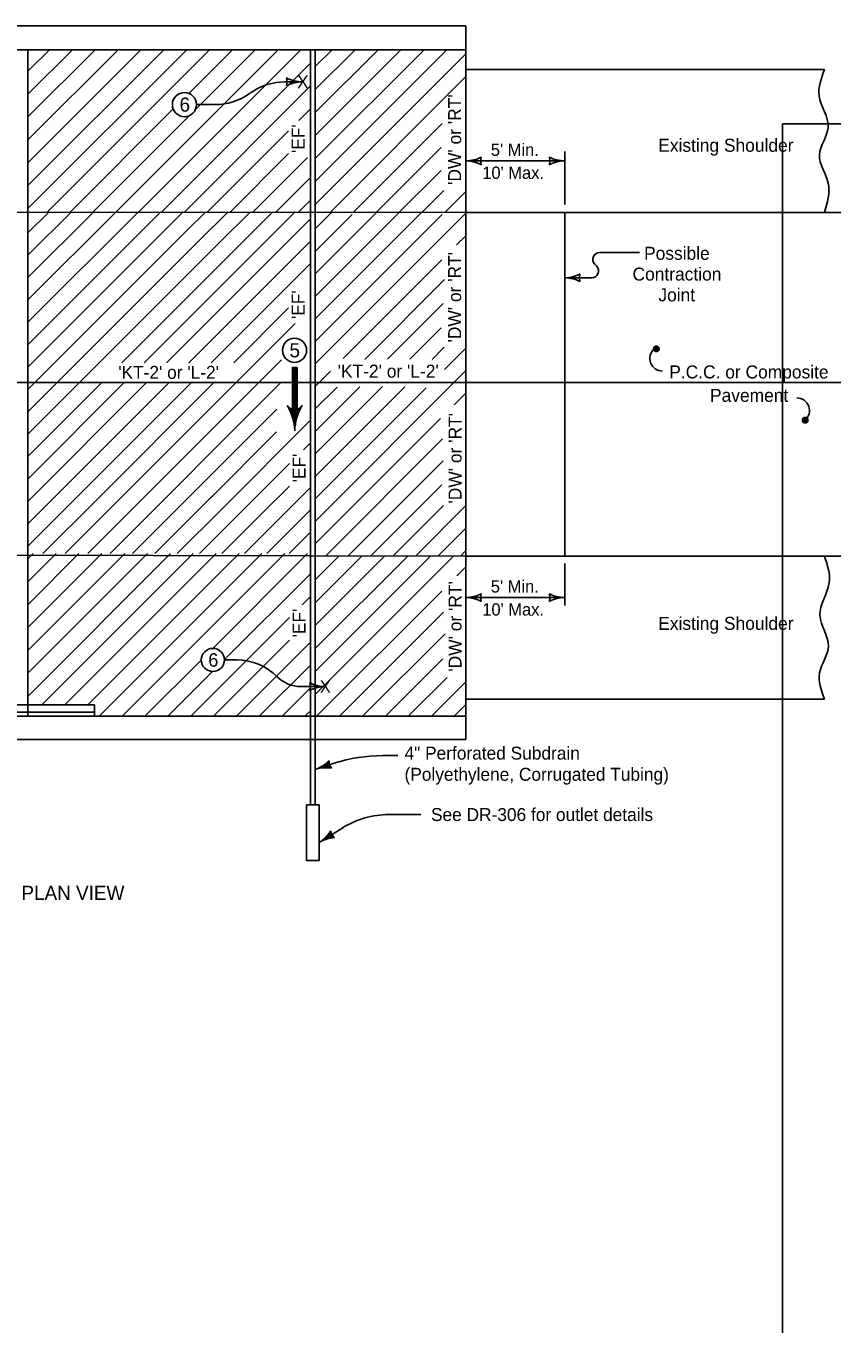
# Model space of a CAD drawing. Extents: x 5546 to 81668, y 3174 to 15999.
# Drawn here: x 20614 to 21661, y 14241 to 15927 of the extents above; entities that cross this region are included whole.
import ezdxf

# ---------------------------------------------------------------- set-up
doc = ezdxf.new("R2010")
doc.units = 0
for name, color, linetype in [('Level 61', 7, 'Continuous'), ('PS_BOLT', 7, 'Continuous'), ('PS_DAWA', 7, 'Continuous'), ('PS_DIM', 7, 'Continuous')]:
    doc.layers.add(name, color=color, linetype=linetype)

msp = doc.modelspace()

# ---------------------------------------------------------------- linework, layer by layer
msp.add_line((20246, 15896.5), (21185.1, 15896.5))
at = {"layer": 'Level 61'}
msp.add_lwpolyline([(21596.3, 15800.4), (24731.3, 15800.4), (24731.3, 13780.4), (21596.3, 13780.4)], close=True, dxfattribs=at)
at = {"layer": 'PS_BOLT'}
for p, q in [((21185.1, 15732.5), (21185.1, 15774.1)), ((21185.1, 15684.9), (21185.1, 15238.7)), ((21313.4, 15684.9), (21313.4, 15238.7)), ((20975.8, 15262.4), (20983.1, 15269.7)), ((19806.8, 15241.9), (21185.1, 15238.7)), ((20887.6, 15103.8), (20871.3, 15103.8)), ((21002.1, 15069.2), (20970.8, 15069.2)), ((21096.5, 14979.6), (21076.9, 14979.6)), ((21126.6, 14903), (21085, 14903)), ((21025, 14885.7), (20994.4, 14866.5))]:
    msp.add_line(p, q, dxfattribs=at)
for centre, radius, start, end in [((21440.5, 15495.6), 16.5, 131.3092, 270), ((21614.9, 15427.7), 16.5, 311.309, 90), ((20887.6, 15030.4), 73.4, 45, 90), ((20970.8, 15113.3), 44.1, 225, 270), ((21076.9, 14774), 205.6, 90, 107.8594), ((21085, 14789.9), 113.1, 90, 122.0832)]:
    msp.add_arc(centre, radius, start, end, dxfattribs=at)
at = {"layer": 'PS_DAWA'}
for p, q in [((21185.1, 15752.1), (21313.4, 15752.1)), ((21313.4, 15695.6), (21313.4, 15764.4)), ((21410.5, 15633.2), (21359, 15633.2)), ((21352.4, 15618.1), (21355, 15615.2)), ((21348.4, 15600.2), (21313.4, 15600.2)), ((21313.4, 15174.4), (21313.4, 15228.9)), ((21185.1, 15184.9), (21313.4, 15184.9))]:
    msp.add_line(p, q, dxfattribs=at)
for centre, radius, start, end in [((21185.1, 15794.6), 42.5, 270, 298.0725), ((21185.1, 15709.6), 42.5, 61.9275, 90), ((21220.7, 15752.1), 16.4, 162.2666, 197.7334), ((21277.7, 15752.1), 16.4, 342.2666, 17.7333), ((21313.4, 15794.6), 42.5, 241.9275, 270), ((21313.4, 15709.6), 42.5, 90, 118.0725), ((21359, 15624.2), 9, 90, 222.4139), ((21348.4, 15609.2), 9, 270, 42.4139), ((21313.4, 15642.7), 42.5, 270, 298.0725), ((21313.4, 15557.7), 42.5, 61.9275, 90), ((21349, 15600.2), 16.4, 162.2666, 197.7334), ((21185.1, 15227.4), 42.5, 270, 298.0725), ((21185.1, 15142.4), 42.5, 61.9275, 90), ((21220.7, 15184.9), 16.4, 162.2666, 197.7334), ((21277.7, 15184.9), 16.4, 342.2666, 17.7333), ((21313.4, 15227.4), 42.5, 241.9275, 270), ((21313.4, 15142.4), 42.5, 90, 118.0725)]:
    msp.add_arc(centre, radius, start, end, dxfattribs=at)
at = {"layer": 'PS_DIM'}
for p, q in [((19870.2, 15927.3), (21185.1, 15927.3)), ((21185.1, 15927.3), (21185.1, 15871.1)), ((20246, 15896.5), (20616.1, 15896.5)), ((20616.1, 15896.5), (20246, 15896.5)), ((20616.1, 15896.5), (20616.1, 15241.9)), ((20616.1, 15690.3), (20822.3, 15896.5)), ((20616.1, 15720), (20792.6, 15896.5)), ((20616.1, 15749.7), (20762.9, 15896.5)), ((20616.1, 15779.4), (20733.2, 15896.5)), ((20616.1, 15809.1), (20703.5, 15896.5)), ((20616.1, 15838.8), (20673.8, 15896.5)), ((20616.1, 15868.5), (20644.1, 15896.5)), ((20641.5, 15686), (20852, 15896.5)), ((20730.6, 15686), (20941.1, 15896.5)), ((20760.3, 15686), (20970.8, 15896.5)), ((20824.9, 15839.7), (20881.7, 15896.5)), ((20833.6, 15818.8), (20911.4, 15896.5)), ((20983.1, 15686), (20983.1, 15896.5)), ((20989.2, 15896.5), (20989.2, 15686)), ((20989.2, 15725.3), (21160.4, 15896.5)), ((20989.2, 15755.2), (21130.6, 15896.5)), ((20989.2, 15785), (21100.7, 15896.5)), ((20989.2, 15814.9), (21070.9, 15896.5)), ((20989.2, 15844.7), (21041, 15896.5)), ((20989.2, 15874.6), (21011.2, 15896.5)), ((20989.2, 15695.5), (21185.1, 15891.3)), ((21185.1, 15684.9), (21185.1, 15896.5)), ((20616.1, 15686), (20616.1, 15871.1)), ((20790, 15686), (20983.1, 15879.1)), ((20983.1, 15686), (20983.1, 15871.1)), ((20989.2, 15686), (20989.2, 15871.1)), ((21185.1, 15870.9), (21650.9, 15870.9)), ((21185.1, 15684.9), (21185.1, 15870.9)), ((20819.7, 15686), (20983.1, 15849.4)), ((20972.8, 15854.7), (20950, 15854.7)), ((21008.6, 15684.9), (21185.1, 15861.5)), ((20905.8, 15840.8), (20903.5, 15839.2)), ((20671.2, 15686), (20804.9, 15819.7)), ((20859.3, 15825.2), (20835.1, 15825.2)), ((20967.9, 15804.5), (20983.1, 15819.7)), ((20700.9, 15686), (20826.2, 15811.3)), ((21038.4, 15684.9), (21154.2, 15800.7)), ((20849.4, 15686), (20954.7, 15791.3)), ((21068.3, 15684.9), (21152.8, 15769.5)), ((20879.1, 15686), (20954.7, 15761.6)), ((20908.8, 15686), (20979.1, 15756.4)), ((21098.1, 15684.9), (21152.8, 15739.6)), ((20938.5, 15686), (20983.1, 15730.6)), ((20968.2, 15686), (20983.1, 15700.9)), ((21127.9, 15684.9), (21156.4, 15713.4)), ((21157.8, 15684.9), (21185.1, 15712.2)), ((21185.1, 15684.9), (19760.1, 15686)), ((20616.1, 15658.6), (20643.5, 15686)), ((20616.1, 15629.6), (20672.5, 15686)), ((20616.1, 15600.5), (20701.6, 15686)), ((20616.1, 15571.4), (20730.7, 15686)), ((20616.1, 15542.4), (20759.8, 15686)), ((20616.1, 15513.3), (20788.8, 15686)), ((20616.1, 15484.2), (20817.9, 15686)), ((20820.7, 15659.8), (20847, 15686)), ((20838.1, 15648.1), (20876.1, 15686)), ((20864.1, 15645), (20905.1, 15686)), ((20912.4, 15664.2), (20934.2, 15686)), ((20954.8, 15677.5), (20963.3, 15686)), ((20983.1, 15241.9), (20983.1, 15686)), ((20989.2, 15241.9), (20989.2, 15686)), ((20989.2, 15546.8), (21127.4, 15684.9)), ((20989.2, 15663.6), (21010.6, 15684.9)), ((20989.2, 15605.2), (21069, 15684.9)), ((20989.2, 15576), (21098.2, 15684.9)), ((20989.2, 15488.3), (21185.1, 15684.2)), ((20989.2, 15517.5), (21154.2, 15682.5)), ((20989.2, 15634.4), (21037.3, 15682.5)), ((21185.1, 15684.9), (21685.9, 15684.9)), ((20738, 15489.8), (20912.4, 15664.2)), ((20767.1, 15489.8), (20954.8, 15677.5)), ((20796.2, 15489.8), (20983.1, 15676.7)), ((20616.1, 15455.1), (20820.7, 15659.8)), ((20616.1, 15426.1), (20838.1, 15648.1)), ((20825.3, 15489.8), (20983.1, 15647.7)), ((21173, 15642.9), (21185.1, 15654.9)), ((20729.6, 15510.5), (20864.1, 15645)), ((20864.1, 15645), (20857.2, 15638.1)), ((20854.3, 15489.8), (20983.1, 15618.6)), ((21025.5, 15495.4), (21153.9, 15623.7)), ((21053.7, 15494.3), (21157.3, 15597.9)), ((20615.7, 15576.1), (20616.1, 15576.5)), ((21083, 15494.4), (21155.5, 15566.9)), ((20883.4, 15489.8), (20954.7, 15561.1)), ((20664.6, 15241.9), (20963.3, 15540.7)), ((21112.3, 15494.5), (21153, 15535.2)), ((20616.1, 15397), (20729.6, 15510.5)), ((21141.1, 15494.1), (21157, 15510)), ((21157.3, 15481.1), (21185.1, 15508.8)), ((20693.7, 15241.9), (20945.3, 15493.6)), ((20962.7, 15429.3), (20962.7, 15483.8)), ((20989.2, 15283.8), (21185.1, 15479.6)), ((20989.2, 15459.1), (21009.2, 15479)), ((20246, 15464), (21723.8, 15464)), ((20616.1, 15367.9), (20712.2, 15464)), ((20616.1, 15338.8), (20741.3, 15464)), ((20616.1, 15309.8), (20770.3, 15464)), ((20616.1, 15280.7), (20799.4, 15464)), ((20690.4, 15325.9), (20828.5, 15464)), ((20705, 15311.4), (20857.6, 15464)), ((20722.7, 15241.9), (20944.8, 15464)), ((20989.2, 15371.4), (21076.9, 15459.1)), ((20989.2, 15400.7), (21047.1, 15458.5)), ((20989.2, 15342.2), (21105.5, 15458.5)), ((20989.2, 15429.9), (21017.7, 15458.3)), ((20989.2, 15313), (21133.6, 15457.4)), ((21169.8, 15435.1), (21185.1, 15450.4)), ((20751.8, 15241.9), (20939.4, 15429.5)), ((20959.6, 15429.4), (20959.6, 15429.4)), ((20966, 15429.5), (20966, 15429.5)), ((20868.2, 15300.2), (20983.1, 15415.1)), ((20989.2, 15254.6), (21152.2, 15417.5)), ((20851.8, 15312.8), (20938.9, 15400)), ((20974, 15376.9), (20983.1, 15386)), ((21002.6, 15238.7), (21154.8, 15390.9)), ((21031.8, 15238.7), (21155.5, 15362.4)), ((20896.7, 15299.7), (20955.9, 15358.8)), ((20919.2, 15293.1), (20955.9, 15329.7)), ((20935.7, 15280.4), (20983.1, 15327.8)), ((21061, 15238.7), (21153.6, 15331.3)), ((20616.1, 15251.6), (20690.4, 15325.9)), ((20635.5, 15241.9), (20705, 15311.4)), ((20780.9, 15241.9), (20855.9, 15317)), ((20810, 15241.9), (20868.2, 15300.2)), ((20839, 15241.9), (20896.7, 15299.7)), ((20868.1, 15241.9), (20923.6, 15297.5)), ((20951.2, 15266.9), (20983.1, 15298.8)), ((21090.2, 15238.7), (21155.9, 15304.4)), ((21119.4, 15238.7), (21185.1, 15304.3)), ((20897.2, 15241.9), (20938.8, 15283.6)), ((20926.3, 15241.9), (20951.2, 15266.9)), ((20955.3, 15241.9), (20975.8, 15262.4)), ((21148.7, 15238.7), (21185.1, 15275.1)), ((21177.9, 15238.7), (21185.1, 15245.9)), ((20616.1, 15241.9), (20616.1, 15056.9)), ((20616.1, 15241.9), (20616.1, 15031.5)), ((20616.1, 15086.6), (20771.5, 15241.9)), ((20616.1, 15116.2), (20741.8, 15241.9)), ((20616.1, 15175.6), (20682.4, 15241.9)), ((20616.1, 15205.3), (20652.7, 15241.9)), ((20616.1, 15235), (20623, 15241.9)), ((20616.1, 15145.9), (20712.1, 15241.9)), ((20616.2, 15056.9), (20801.2, 15241.9)), ((20634.3, 15045.4), (20830.9, 15241.9)), ((20664, 15045.4), (20860.6, 15241.9)), ((20693.7, 15045.4), (20890.3, 15241.9)), ((20708.7, 15030.7), (20920, 15241.9)), ((20738.4, 15030.7), (20949.7, 15241.9)), ((20856.3, 15118.8), (20979.4, 15241.9)), ((20983.1, 15031.5), (20983.1, 15241.9)), ((20989.2, 15241.9), (20989.2, 15031.5)), ((20989.2, 15058.8), (21169.1, 15238.7)), ((20989.2, 15088.7), (21139.2, 15238.7)), ((20989.2, 15118.5), (21109.4, 15238.7)), ((20989.2, 15148.4), (21079.5, 15238.7)), ((20989.2, 15178.2), (21049.7, 15238.7)), ((20989.2, 15208.1), (21019.8, 15238.7)), ((21185.1, 15238.7), (21685.9, 15238.7)), ((21185.1, 15031.5), (21185.1, 15238.7)), ((20871.1, 15104), (20983.1, 15215.9)), ((21173.2, 15213), (21185.1, 15224.8)), ((20991.7, 15031.5), (21153.6, 15193.3)), ((20972.3, 15175.4), (20983.1, 15186.2)), ((20827.5, 15030.7), (20955.9, 15159.1)), ((21021.6, 15031.5), (21156.1, 15166)), ((20858, 15031.5), (20955.9, 15129.4)), ((20887.7, 15031.5), (20983.1, 15126.8)), ((21051.4, 15031.5), (21157.9, 15137.9)), ((20768.1, 15030.7), (20841.5, 15104)), ((20917.4, 15031.5), (20983.1, 15097.1)), ((21081.3, 15031.5), (21155.1, 15105.3)), ((20797.8, 15030.7), (20856.4, 15089.2)), ((21111.1, 15031.5), (21160.8, 15081.2)), ((21141, 15031.5), (21185.1, 15075.6)), ((20947.1, 15031.5), (20983.1, 15067.4)), ((19926.7, 15045.4), (20702.4, 15045.4)), ((20702.4, 15030.7), (20702.4, 15045.4)), ((21170.8, 15031.5), (21185.1, 15045.8)), ((21185.1, 15052.7), (21650.9, 15052.7)), ((21185.1, 15000.6), (21185.1, 15052.7)), ((19945.6, 15035.8), (20702.4, 15035.8)), ((19955.8, 15030.7), (21185.1, 15030.7)), ((20976.8, 15031.5), (20983.1, 15037.8)), ((20983.1, 15031.5), (20983.1, 14915.8)), ((20989.2, 15031.5), (20989.2, 14915.8)), ((20283, 15000.6), (21185.1, 15000.6)), ((21013.8, 14969.7), (20989.2, 14961.7)), ((20989.2, 14961.7), (21008.1, 14967.8)), ((20977.9, 14915.8), (20994.4, 14915.8)), ((20977.9, 14915.8), (20977.9, 14843.3)), ((20994.4, 14915.8), (20994.4, 14843.3)), ((20994.4, 14866.5), (21011.1, 14877)), ((20977.9, 14843.3), (20994.4, 14843.3))]:
    msp.add_line(p, q, dxfattribs=at)
for points in [[(20983.1, 15686), (20983.1, 15686)], [(21432.1, 15504.7), (21433.3, 15505.2), (21435.2, 15505.8), (21435.6, 15507.7), (21435.3, 15509.4), (21434.1, 15511), (21432.3, 15510.8), (21430.4, 15510.5), (21429.5, 15509), (21429.3, 15507.4), (21430.4, 15505.3), (21431.8, 15505.2), (21433.7, 15505.6), (21435.3, 15506.9), (21435.2, 15508.7), (21434, 15510.1), (21432.3, 15510.3), (21430.4, 15509.9), (21430.1, 15508.8), (21429.7, 15507.6), (21430.6, 15506), (21432, 15506), (21433.6, 15506.3), (21434.7, 15507.2), (21434.2, 15508.7), (21433, 15509.7), (21431.4, 15509.7), (21431, 15508.9), (21430.5, 15507.9), (21431.3, 15506.6), (21432.4, 15506.4), (21433.5, 15506.9), (21433.6, 15508.1), (21433, 15508.9), (21431.9, 15509.2), (21431.4, 15508.8), (21431.1, 15508.1), (21431.7, 15507.2), (21432.4, 15507), (21433.1, 15507.4), (21433, 15508.1), (21432.5, 15508.5), (21431.7, 15508.5), (21431.7, 15507.9), (21432.4, 15507.6)], [(20965.8, 15429.4), (20965.8, 15483.8), (20959.6, 15483.8), (20959.6, 15429.4), (20964.9, 15429.6), (20965.1, 15483.1), (20960.2, 15483), (20960.4, 15430.6), (20964.1, 15430.5), (20964.3, 15482.4), (20961, 15482.2), (20961, 15431.3), (20963.3, 15431.1), (20963.6, 15481.8), (20961.8, 15481.7), (20961.8, 15432)], [(20969.8, 15430.9), (20966.1, 15428.6), (20960.7, 15428.3), (20956, 15430.3), (20959.4, 15422.2), (20962.1, 15412.8), (20962.7, 15410.2), (20964.1, 15417), (20967.5, 15426.9), (20969, 15429.8), (20957.6, 15428.7), (20962.5, 15414.2), (20966.8, 15428.4), (20958.9, 15427.8), (20962.6, 15417.9), (20964.8, 15427), (20960.3, 15427.4), (20962.3, 15421.1), (20963.7, 15425.9), (20961.5, 15426.2), (20962.2, 15423.9)], [(21625.5, 15411.9), (21626.7, 15412.5), (21628.6, 15413.1), (21629, 15415), (21628.7, 15416.7), (21627.5, 15418.3), (21625.7, 15418.1), (21623.8, 15417.8), (21622.9, 15416.3), (21622.7, 15414.7), (21623.9, 15412.6), (21625.3, 15412.4), (21627.2, 15412.9), (21628.7, 15414.1), (21628.7, 15415.9), (21627.4, 15417.4), (21625.7, 15417.6), (21623.8, 15417.2), (21623.5, 15416.1), (21623.2, 15414.8), (21624.1, 15413.3), (21625.4, 15413.3), (21627, 15413.6), (21628.2, 15414.4), (21627.6, 15416), (21626.4, 15416.9), (21624.8, 15417), (21624.4, 15416.1), (21623.9, 15415.2), (21624.7, 15413.9), (21625.9, 15413.6), (21626.9, 15414.2), (21627, 15415.4), (21626.4, 15416.2), (21625.3, 15416.5), (21624.8, 15416), (21624.5, 15415.4), (21625.1, 15414.5), (21625.8, 15414.3), (21626.6, 15414.7), (21626.4, 15415.3), (21625.9, 15415.8), (21625.2, 15415.7), (21625.2, 15415.2), (21625.8, 15414.9)], [(20983.1, 15241.9), (20983.1, 15241.9)], [(21008.8, 14964.2), (21007, 14967.5), (21006.6, 14971.2), (21003, 14967.9), (20996.8, 14964.2), (21004.5, 14964.8), (21008.1, 14964.5), (21006.3, 14967.3), (21005.9, 14969.6), (21003.5, 14967.4), (21000.1, 14965.3), (21004.4, 14965.4), (21006.7, 14965.4), (21005.4, 14968.2), (21003, 14966.2), (21005.4, 14966.2), (21005.1, 14967.3), (21004.2, 14966.6)], [(21012.7, 14873.7), (21010.1, 14876.4), (21008.8, 14880), (21006.2, 14875.8), (21001.1, 14870.8), (21008.4, 14873.3), (21012, 14873.8), (21009.6, 14876.1), (21008.6, 14878.3), (21006.8, 14875.5), (21004.1, 14872.6), (21008.2, 14873.8), (21010.4, 14874.3), (21008.4, 14876.8), (21006.6, 14874.2), (21008.9, 14874.8), (21008.4, 14875.8), (21007.7, 14874.9)]]:
    msp.add_lwpolyline(points, dxfattribs=at)
for centre, radius in [((20819.4, 15825.2), 15.7), ((20962.4, 15506.1), 15.7), ((21432.4, 15508), 3.62), ((21625.8, 15415.3), 3.62), ((20856.3, 15103.8), 15)]:
    msp.add_circle(centre, radius, dxfattribs=at)
for centre, radius, start, end in [((20950.1, 15777.6), 77.1, 90, 124.9993), ((20935.6, 15854.7), 17.1, 342.2666, 17.7334), ((20972.8, 15899.1), 44.4, 241.9275, 270), ((20935.6, 15854.7), 17.1, 342.2666, 17.7334), ((20972.8, 15899.1), 44.4, 241.9275, 270), ((20972.8, 15810.3), 44.4, 90, 118.0725), ((20972.8, 15810.3), 44.4, 90, 118.0725), ((20859.3, 15902.3), 77.1, 270, 304.9999), ((20962.7, 15440.6), 11.6, 211.7147, 328.2853), ((20896.4, 15399.6), 66.3, 1.6842, 31.7143), ((21028.9, 15399.6), 66.3, 148.2857, 178.3158), ((20966.7, 15069.2), 16.3, 342.2666, 17.7333), ((21002.1, 15111.5), 42.3, 241.9275, 270), ((21002.1, 15027), 42.3, 90, 118.0725), ((20975.9, 15003.3), 43.7, 287.8585, 315.9309), ((21024.1, 14973), 16.9, 180.1251, 215.5918), ((21002.6, 14920.2), 43.7, 79.786, 107.8585), ((20971.2, 14903.5), 43.7, 302.0841, 330.1566), ((21017.6, 14829.5), 43.7, 94.0116, 122.0841), ((21025.4, 14886), 16.9, 194.3508, 229.8175)]:
    msp.add_arc(centre, radius, start, end, dxfattribs=at)
for points in [[(21650.9, 15870.9), (21643.9, 15836.5), (21655.7, 15795.6), (21644.3, 15759.9), (21655.7, 15723.2), (21650.9, 15684.9)], [(21650.9, 15238.7), (21657, 15203.8), (21644.9, 15161.8), (21656, 15121.8), (21644.5, 15087.2), (21650.9, 15052.7)]]:
    msp.add_spline(points, degree=3, dxfattribs=at)

# ---------------------------------------------------------------- texts
at = {"layer": 'PS_BOLT'}
for s, height, p in [('X', 16.8, (20965.7, 15846.3)), ('6', 18.4, (20813, 15816)), ('Existing Shoulder', 16.884, (21434.9, 15763.9)), ('Possible', 16.88, (21416.5, 15623.6)), ('Contraction', 16.884, (21401.5, 15596.6)), ('Joint', 16.88, (21435.1, 15569.6)), ('5', 18.4, (20955.8, 15496.9)), ("'KT-2' or 'L-2'", 16.8, (20733.4, 15469)), ("'KT-2' or 'L-2'", 16.884, (21018.4, 15470.5)), ('P.C.C. or Composite', 16.884, (21449.2, 15469.5)), ('Pavement', 16.88, (21502.2, 15439.1)), ('Existing Shoulder', 16.884, (21434.9, 15142.9)), ('6', 17.5, (20850.4, 15095.1)), ('X', 16, (20995.3, 15061.2)), ('4" Perforated Subdrain ', 16.8, (21105.3, 14974.4)), ('(Polyethylene, Corrugated Tubing)', 16.8, (21105.3, 14946.9)), ('See DR-306 for outlet details', 16.8, (21139.7, 14894.6)), ('PLAN VIEW', 18.37, (20607.6, 14792.1))]:
    msp.add_text(s, height=height, dxfattribs=at).set_placement(p)
for s, height, p in [("'DW' or 'RT'", 16.884, (21178.8, 15720.9)), ("'EF'", 16.8, (20975.5, 15762.3)), ("'DW' or 'RT'", 16.884, (21178.8, 15516.2)), ("'EF'", 16.8, (20975.5, 15546.6)), ("'DW' or 'RT'", 16.884, (21179.4, 15307)), ("'EF'", 16.8, (20976.7, 15334.6)), ("'DW' or 'RT'", 16.884, (21179.4, 15088.6)), ("'EF'", 16.8, (20976.7, 15133.1))]:
    msp.add_text(s, height=height, rotation=90, dxfattribs=at).set_placement(p)
at = {"layer": 'PS_DAWA'}
for s, p in [("5' Min.", (21217.4, 15758.6)), ("10' Max.", (21206.3, 15728.7)), ("5' Min.", (21217.4, 15191.4)), ("10' Max.", (21206.3, 15161.4))]:
    msp.add_text(s, height=16, dxfattribs=at).set_placement(p)

doc.saveas('drawing.dxf')
